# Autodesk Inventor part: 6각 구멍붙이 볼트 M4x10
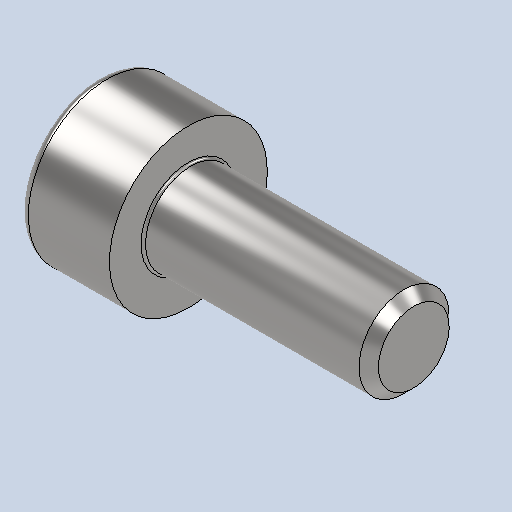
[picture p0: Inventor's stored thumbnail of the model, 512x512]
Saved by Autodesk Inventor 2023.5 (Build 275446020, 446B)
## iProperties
Created: 2026-07
Part Number: 6각 구멍붙이 볼트 M4x10
Material: 강철, 연강
Description: 6각머리 태핑 나사
Document SubType Name: Modeling
Designer: mirae
Density: 7.86 g/cm^3
Appearance: 기본값
Author: jhkim
Revision Number: 1
Sending System: Autodesk Inventor 2027
Preprocessor: ST-DEVELOPER v20.1
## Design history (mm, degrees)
node "6각 구멍붙이 볼트 M4x101"
node "솔리드1"
body "Solid1"
